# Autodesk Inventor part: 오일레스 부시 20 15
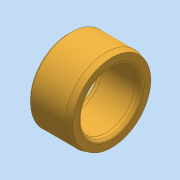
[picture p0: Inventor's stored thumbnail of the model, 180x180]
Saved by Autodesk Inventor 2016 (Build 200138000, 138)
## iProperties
Created: 2024-08
Part Number: 오일레스 부시 20 15
Material: 일반
Document SubType Name: Modeling
Designer: pc-7
Density: 1 g/cm^3
Appearance: 기본값
Author: jhkim
Sending System: Autodesk Inventor 2025
Preprocessor: ST-DEVELOPER v20
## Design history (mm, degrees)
node "오일레스 부시 20 151"
node "솔리드2"
node "솔리드1"
